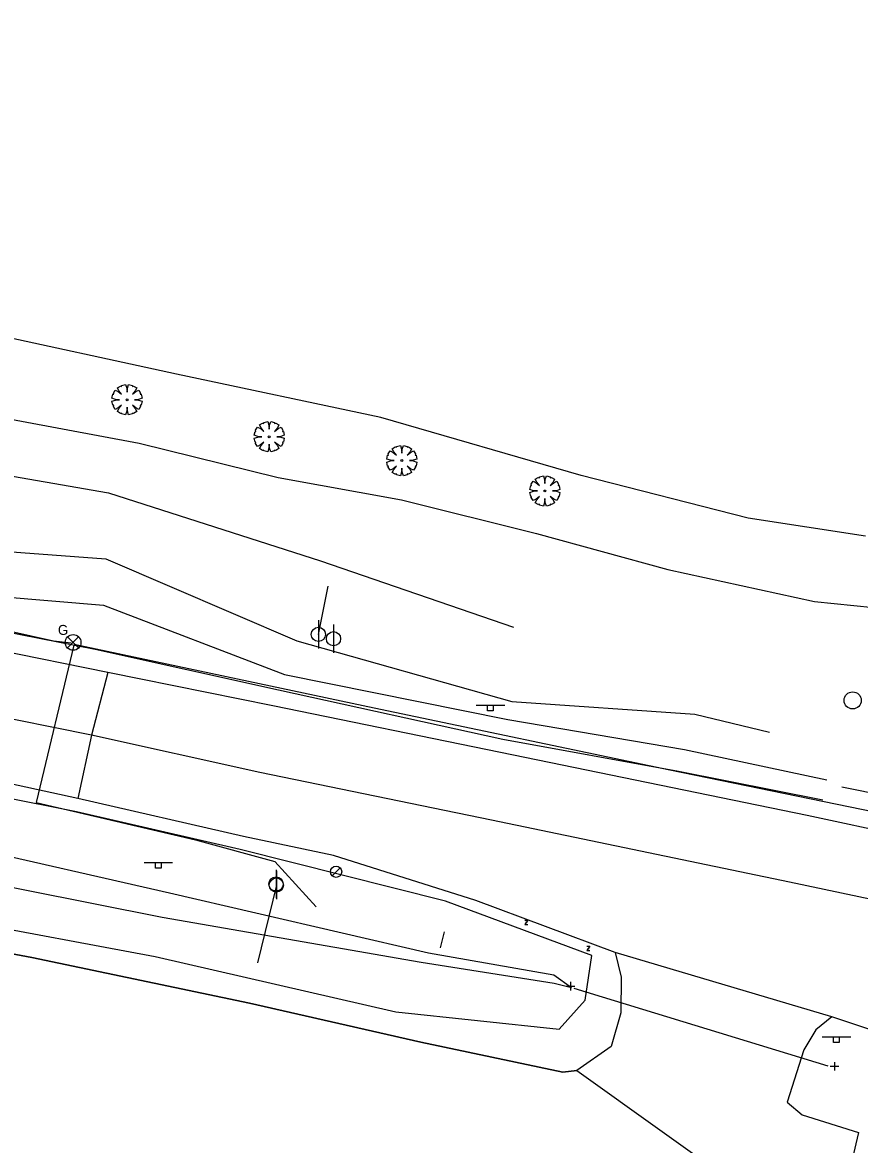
# Model space of a CAD drawing. Extents: x 1158469 to 1165378, y 609843 to 611748.
# Drawn here: x 1164983.4 to 1165130.6, y 610051.9 to 610249.2 of the extents above; entities that cross this region are included whole.
import ezdxf

# ---------------------------------------------------------------- set-up
doc = ezdxf.new("R2010")
doc.units = 0
for name, color, linetype in [('Exterior Boundary', 7, 'Continuous'), ('S_Drainage_Culvert_Top', 7, 'Continuous'), ('S_Drainage_Invert', 7, 'Continuous'), ('S_Ground_Elevation', 7, 'Continuous'), ('S_Ground_LevelString', 7, 'Continuous'), ('S_Ground_SpotElevation', 7, 'Continuous'), ('S_Property_IronPipeFound', 7, 'Continuous'), ('S_Roadway_Centerline', 7, 'Continuous'), ('S_Roadway_Drive_Paved', 7, 'Continuous'), ('S_Roadway_Edge_Pavement', 7, 'Continuous'), ('S_Traffic_Sign_DoublePost', 7, 'Continuous'), ('S_Traffic_Sign_SinglePost', 7, 'Continuous'), ('S_Trees_Decid_NonPay', 7, 'Continuous'), ('S_Utilities_Gas_Gate', 7, 'Continuous'), ('S_Utilities_GuyWire3', 7, 'Continuous'), ('S_Utilities_Pole_Power', 7, 'Continuous'), ('S_Utilities_UG_Gas_Line', 7, 'Continuous'), ('S_Utilities_UG_Water_Shutoff', 7, 'Continuous')]:
    doc.layers.add(name, color=color, linetype=linetype)

msp = doc.modelspace()

# ---------------------------------------------------------------- linework, layer by layer
at = {"layer": 'Exterior Boundary'}
for points in [[(1165131.67, 610158.89), (1165111.05, 610162.04), (1165081.66, 610169.51), (1165046.46, 610179.72), (1165010.53, 610187.31), (1164975.93, 610194.85), (1164954.17, 610199.11), (1164924.19, 610204.21), (1164911.82, 610196.02), (1164907.99, 610190.98), (1164903.83, 610193.7), (1164863.2, 610204)], [(1164887.39, 610105.37), (1164928.57, 610096.9), (1164949.13, 610091.57), (1164985.09, 610084.83), (1165023.36, 610076.76), (1165053.51, 610069.94), (1165078.44, 610064.65), (1165080.91, 610064.92), (1165125.5, 610033.08), (1165315.71, 609929.68)]]:
    msp.add_lwpolyline(points, dxfattribs=at)
at = {"layer": 'S_Drainage_Culvert_Top'}
msp.add_lwpolyline([(1165125.09, 610065.68), (1165080.42, 610079.35)], dxfattribs=at)
at = {"layer": 'S_Drainage_Invert'}
for p, q in [((1165079.82, 610080.51), (1165079.82, 610079.01)), ((1165079.07, 610079.76), (1165080.57, 610079.76)), ((1165126.2, 610066.43), (1165126.2, 610064.93)), ((1165125.45, 610065.68), (1165126.95, 610065.68))]:
    msp.add_line(p, q, dxfattribs=at)
at = {"layer": 'S_Ground_Elevation'}
for points in [[(1165131.67, 610158.89), (1165111.05, 610162.04), (1165081.66, 610169.51), (1165046.46, 610179.72), (1165010.53, 610187.31), (1164975.93, 610194.85), (1164954.17, 610199.11), (1164924.19, 610204.21), (1164911.82, 610196.02), (1164928.99, 610192.61), (1164954.02, 610185.41), (1164976.94, 610180.26), (1165003.93, 610175.22), (1165028.37, 610169.19), (1165050.08, 610165.24), (1165073.84, 610159.31), (1165096.89, 610152.98), (1165122.71, 610147.36), (1165133.09, 610146.34)], [(1164949.24, 610096.19), (1164972.18, 610091.41), (1165006.8, 610084.96), (1165049.11, 610075.28), (1165077.78, 610072.21), (1165082.39, 610077.32), (1165083.55, 610085.15), (1165057.81, 610094.68), (1165021.71, 610103.76), (1164992.93, 610110.39), (1164953.46, 610118.26), (1164916.46, 610126.06), (1164891.26, 610129.22), (1164870.42, 610136.28), (1164819.53, 610147.22), (1164777.52, 610154.18), (1164692.53, 610173.85), (1164663.65, 610179.23), (1164613.39, 610190.6), (1164600.18, 610192.25)], [(1164966.43, 610172.04), (1164998.59, 610166.47), (1165035.82, 610154.51), (1165069.8, 610142.86)], [(1164962.64, 610157.49), (1164998.12, 610154.87), (1165031.67, 610140.45), (1165069.48, 610129.78), (1165101.64, 610127.55), (1165114.79, 610124.42)], [(1165341.63, 610152.38), (1165338.28, 610137.27), (1165328.96, 610121.76), (1165325.7, 610114.21), (1165322.7, 610114.67), (1165317.16, 610108.11), (1165300.9, 610100.28), (1165278.07, 610094.59), (1165255.25, 610093.27), (1165234.36, 610095.8), (1165209.94, 610099.32), (1165192.02, 610102.23), (1165159.8, 610108.25), (1165127.49, 610114.72)], [(1164961.29, 610149.76), (1164997.7, 610146.75), (1165029.5, 610134.54), (1165068.79, 610126.62), (1165099.84, 610121.37), (1165124.88, 610116.02)], [(1164959.76, 610146.17), (1164996.21, 610138.99), (1165028.47, 610131.87), (1165067.91, 610123.16), (1165098.77, 610117.56), (1165124.14, 610112.54)], [(1164952.23, 610109.23), (1164972.73, 610104.47), (1165009.28, 610096.16), (1165054.81, 610085.61), (1165076.88, 610081.78), (1165079.99, 610079.53)], [(1164950.89, 610103.75), (1164971.74, 610099.12), (1165008, 610091.89), (1165053.56, 610083.98), (1165076.9, 610080.31), (1165079.99, 610079.53)]]:
    msp.add_lwpolyline(points, dxfattribs=at)
at = {"layer": 'S_Ground_LevelString'}
msp.add_lwpolyline([(1164998.45, 610134.89), (1164995.59, 610123.89), (1164993.19, 610112.73)], dxfattribs=at)
at = {"layer": 'S_Ground_SpotElevation'}
for p, q in [((1165071.75, 610091.39), (1165072.28, 610091.39)), ((1165072.28, 610091.39), (1165071.75, 610090.61)), ((1165071.75, 610090.61), (1165072.27, 610090.61)), ((1165071.86, 610091), (1165072.17, 610091)), ((1165082.68, 610086.8), (1165083.21, 610086.8)), ((1165083.21, 610086.8), (1165082.68, 610086.02)), ((1165082.68, 610086.02), (1165083.21, 610086.02)), ((1165082.79, 610086.41), (1165083.1, 610086.41))]:
    msp.add_line(p, q, dxfattribs=at)
at = {"layer": 'S_Property_IronPipeFound'}
msp.add_circle((1165129.41, 610130), 1.5, dxfattribs=at)
at = {"layer": 'S_Roadway_Centerline'}
msp.add_lwpolyline([(1165322.92, 610055.12), (1165282.59, 610063.58), (1165267.59, 610066.74), (1165234.97, 610073.48), (1165207.29, 610078.95), (1165170.95, 610086.9), (1165118.3, 610098.03), (1165065.91, 610108.93), (1165025.19, 610117.35), (1164995.59, 610123.89), (1164956.04, 610131.83), (1164919.32, 610140.12), (1164874.11, 610149.34), (1164822.77, 610160.96), (1164779.77, 610169.22), (1164696.7, 610187.78), (1164657.25, 610196.14), (1164616.44, 610205.3), (1164588.01, 610211.13), (1164540.84, 610220.89), (1164515.97, 610226.08), (1164470.96, 610235.38), (1164428.02, 610243.9), (1164400.81, 610249.16)], dxfattribs=at)
at = {"layer": 'S_Roadway_Drive_Paved'}
for points in [[(1165087.67, 610085.66), (1165088.73, 610081.37), (1165088.66, 610075.08), (1165086.95, 610069.17), (1165080.91, 610064.92), (1165078.44, 610064.65), (1165053.51, 610069.94), (1165023.36, 610076.76), (1164985.09, 610084.83), (1164949.13, 610091.57), (1164928.57, 610096.9), (1164887.39, 610105.37), (1164871.7, 610110.37), (1164815.65, 610122.37), (1164772.52, 610131.34), (1164687.39, 610149.15), (1164656.83, 610155.47), (1164607.36, 610165.71), (1164581.72, 610171.1)], [(1165125.74, 610074.35), (1165122.94, 610072.11), (1165120.84, 610068.57), (1165117.88, 610059.35), (1165120.55, 610057.16), (1165130.42, 610054.05), (1165125.5, 610033.08)]]:
    msp.add_lwpolyline(points, dxfattribs=at)
at = {"layer": 'S_Roadway_Edge_Pavement'}
for points in [[(1165172.21, 610098.85), (1165121.41, 610109.77), (1165067.49, 610120.81), (1165027.46, 610129.03), (1164998.45, 610134.89), (1164959.14, 610142.85), (1164919.8, 610151.45), (1164879.24, 610159.72)], [(1165176.01, 610057.63), (1165125.74, 610074.35), (1165087.67, 610085.66), (1165063.14, 610094.84), (1165038.13, 610102.71), (1165022.28, 610106.09), (1164993.19, 610112.73), (1164953.01, 610121.48), (1164917.37, 610129.44), (1164871.2, 610138.85)]]:
    msp.add_lwpolyline(points, dxfattribs=at)
at = {"layer": 'S_Traffic_Sign_DoublePost'}
msp.add_lwpolyline([(1165056.93, 610086.51), (1165057.67, 610089.29)], dxfattribs=at)
at = {"layer": 'S_Traffic_Sign_SinglePost'}
for p, q in [((1165063.23, 610129.14), (1165068.23, 610129.14)), ((1165004.83, 610101.49), (1165009.83, 610101.49)), ((1165124.06, 610070.86), (1165129.06, 610070.86))]:
    msp.add_line(p, q, dxfattribs=at)
for points in [[(1165065.23, 610129.14), (1165066.23, 610129.14), (1165066.23, 610128.14), (1165065.23, 610128.14)], [(1165006.83, 610101.49), (1165007.83, 610101.49), (1165007.83, 610100.49), (1165006.83, 610100.49)], [(1165126.06, 610070.86), (1165127.06, 610070.86), (1165127.06, 610069.86), (1165126.06, 610069.86)]]:
    msp.add_lwpolyline(points, close=True, dxfattribs=at)
at = {"layer": 'S_Trees_Decid_NonPay'}
for points in [[(1165000.5, 610182.84), (1164999.8, 610182.9), (1164999.17, 610183.11), (1164999.33, 610183.8), (1164999.49, 610183.8), (1164999.43, 610184.01), (1164999.75, 610184.54), (1165000.28, 610184.28), (1165000.87, 610183.8), (1165000.39, 610184.38), (1165000.12, 610184.92), (1165000.66, 610185.23), (1165000.87, 610185.18), (1165000.87, 610185.34), (1165001.56, 610185.5), (1165001.77, 610184.86), (1165001.82, 610184.17), (1165001.88, 610184.86), (1165002.09, 610185.5), (1165002.78, 610185.34), (1165002.78, 610185.18), (1165002.99, 610185.23), (1165003.53, 610184.92), (1165003.26, 610184.38), (1165002.78, 610183.8), (1165003.37, 610184.28), (1165003.9, 610184.54), (1165004.22, 610184.01), (1165004.16, 610183.8), (1165004.32, 610183.8), (1165004.48, 610183.11), (1165003.84, 610182.9), (1165003.15, 610182.84), (1165003.84, 610182.79), (1165004.48, 610182.58), (1165004.32, 610181.89), (1165004.16, 610181.89), (1165004.22, 610181.67), (1165003.9, 610181.14), (1165003.37, 610181.41), (1165002.78, 610181.89), (1165003.26, 610181.3), (1165003.53, 610180.77), (1165002.99, 610180.45), (1165002.78, 610180.5), (1165002.78, 610180.34), (1165002.09, 610180.18), (1165001.88, 610180.82), (1165001.82, 610181.51), (1165001.77, 610180.82), (1165001.56, 610180.18), (1165000.87, 610180.34), (1165000.87, 610180.5), (1165000.66, 610180.45), (1165000.12, 610180.77), (1165000.39, 610181.3), (1165000.87, 610181.89), (1165000.28, 610181.41), (1164999.75, 610181.14), (1164999.43, 610181.67), (1164999.49, 610181.89), (1164999.33, 610181.89), (1164999.17, 610182.58), (1164999.8, 610182.79), (1165000.5, 610182.84)], [(1165025.5, 610176.34), (1165024.81, 610176.39), (1165024.17, 610176.6), (1165024.33, 610177.29), (1165024.49, 610177.29), (1165024.43, 610177.5), (1165024.75, 610178.04), (1165025.28, 610177.77), (1165025.87, 610177.29), (1165025.39, 610177.88), (1165025.12, 610178.41), (1165025.66, 610178.73), (1165025.87, 610178.67), (1165025.87, 610178.83), (1165026.56, 610178.99), (1165026.77, 610178.36), (1165026.83, 610177.66), (1165026.88, 610178.36), (1165027.09, 610178.99), (1165027.78, 610178.83), (1165027.78, 610178.67), (1165027.99, 610178.73), (1165028.53, 610178.41), (1165028.26, 610177.88), (1165027.78, 610177.29), (1165028.37, 610177.77), (1165028.9, 610178.04), (1165029.22, 610177.5), (1165029.16, 610177.29), (1165029.32, 610177.29), (1165029.48, 610176.6), (1165028.84, 610176.39), (1165028.15, 610176.34), (1165028.84, 610176.28), (1165029.48, 610176.07), (1165029.32, 610175.38), (1165029.16, 610175.38), (1165029.22, 610175.17), (1165028.9, 610174.63), (1165028.37, 610174.9), (1165027.78, 610175.38), (1165028.26, 610174.79), (1165028.53, 610174.26), (1165027.99, 610173.94), (1165027.78, 610174), (1165027.78, 610173.84), (1165027.09, 610173.68), (1165026.88, 610174.32), (1165026.83, 610175.01), (1165026.77, 610174.32), (1165026.56, 610173.68), (1165025.87, 610173.84), (1165025.87, 610174), (1165025.66, 610173.94), (1165025.12, 610174.26), (1165025.39, 610174.79), (1165025.87, 610175.38), (1165025.28, 610174.9), (1165024.75, 610174.63), (1165024.43, 610175.17), (1165024.49, 610175.38), (1165024.33, 610175.38), (1165024.17, 610176.07), (1165024.81, 610176.28), (1165025.5, 610176.34)], [(1165048.81, 610172.15), (1165048.12, 610172.2), (1165047.49, 610172.41), (1165047.65, 610173.1), (1165047.81, 610173.1), (1165047.75, 610173.32), (1165048.07, 610173.85), (1165048.6, 610173.58), (1165049.19, 610173.1), (1165048.71, 610173.69), (1165048.44, 610174.22), (1165048.97, 610174.54), (1165049.19, 610174.48), (1165049.19, 610174.64), (1165049.88, 610174.8), (1165050.09, 610174.17), (1165050.14, 610173.47), (1165050.2, 610174.17), (1165050.41, 610174.8), (1165051.1, 610174.64), (1165051.1, 610174.48), (1165051.31, 610174.54), (1165051.85, 610174.22), (1165051.58, 610173.69), (1165051.1, 610173.1), (1165051.68, 610173.58), (1165052.22, 610173.85), (1165052.54, 610173.32), (1165052.48, 610173.1), (1165052.64, 610173.1), (1165052.8, 610172.41), (1165052.16, 610172.2), (1165051.47, 610172.15), (1165052.16, 610172.09), (1165052.8, 610171.88), (1165052.64, 610171.19), (1165052.48, 610171.19), (1165052.54, 610170.98), (1165052.22, 610170.44), (1165051.68, 610170.71), (1165051.1, 610171.19), (1165051.58, 610170.6), (1165051.85, 610170.07), (1165051.31, 610169.75), (1165051.1, 610169.81), (1165051.1, 610169.65), (1165050.41, 610169.49), (1165050.2, 610170.13), (1165050.14, 610170.82), (1165050.09, 610170.13), (1165049.88, 610169.49), (1165049.19, 610169.65), (1165049.19, 610169.81), (1165048.97, 610169.75), (1165048.44, 610170.07), (1165048.71, 610170.6), (1165049.19, 610171.19), (1165048.6, 610170.71), (1165048.07, 610170.44), (1165047.75, 610170.98), (1165047.81, 610171.19), (1165047.65, 610171.19), (1165047.49, 610171.88), (1165048.12, 610172.09), (1165048.81, 610172.15)], [(1165073.97, 610166.81), (1165073.27, 610166.86), (1165072.64, 610167.07), (1165072.8, 610167.76), (1165072.96, 610167.76), (1165072.9, 610167.98), (1165073.22, 610168.51), (1165073.75, 610168.24), (1165074.34, 610167.76), (1165073.86, 610168.35), (1165073.59, 610168.88), (1165074.13, 610169.2), (1165074.34, 610169.14), (1165074.34, 610169.3), (1165075.03, 610169.46), (1165075.24, 610168.83), (1165075.29, 610168.13), (1165075.35, 610168.83), (1165075.56, 610169.46), (1165076.25, 610169.3), (1165076.25, 610169.14), (1165076.46, 610169.2), (1165077, 610168.88), (1165076.73, 610168.35), (1165076.25, 610167.76), (1165076.84, 610168.24), (1165077.37, 610168.51), (1165077.69, 610167.98), (1165077.63, 610167.76), (1165077.79, 610167.76), (1165077.95, 610167.07), (1165077.31, 610166.86), (1165076.62, 610166.81), (1165077.31, 610166.75), (1165077.95, 610166.54), (1165077.79, 610165.85), (1165077.63, 610165.85), (1165077.69, 610165.64), (1165077.37, 610165.11), (1165076.84, 610165.37), (1165076.25, 610165.85), (1165076.73, 610165.26), (1165077, 610164.73), (1165076.46, 610164.41), (1165076.25, 610164.47), (1165076.25, 610164.31), (1165075.56, 610164.15), (1165075.35, 610164.79), (1165075.29, 610165.48), (1165075.24, 610164.79), (1165075.03, 610164.15), (1165074.34, 610164.31), (1165074.34, 610164.47), (1165074.13, 610164.41), (1165073.59, 610164.73), (1165073.86, 610165.26), (1165074.34, 610165.85), (1165073.75, 610165.37), (1165073.22, 610165.11), (1165072.9, 610165.64), (1165072.96, 610165.85), (1165072.8, 610165.85), (1165072.64, 610166.54), (1165073.27, 610166.75), (1165073.97, 610166.81)]]:
    msp.add_lwpolyline(points, dxfattribs=at)
for centre in [(1165001.82, 610182.84), (1165026.82, 610176.34), (1165050.14, 610172.15), (1165075.29, 610166.81)]:
    msp.add_circle(centre, 0.167, dxfattribs=at)
at = {"layer": 'S_Utilities_Gas_Gate'}
for p, q in [((1164991.37, 610141.15), (1164993.32, 610139.21)), ((1164991.37, 610139.21), (1164993.32, 610141.15))]:
    msp.add_line(p, q, dxfattribs=at)
msp.add_circle((1164992.35, 610140.18), 1.38, dxfattribs=at)
at = {"layer": 'S_Utilities_GuyWire3'}
for points in [[(1165035.47, 610141.6), (1165037.17, 610150.09)], [(1165028.09, 610097.53), (1165028.07, 610097.6)], [(1165028.09, 610097.53), (1165024.74, 610083.85)]]:
    msp.add_lwpolyline(points, dxfattribs=at)
at = {"layer": 'S_Utilities_Pole_Power'}
for p, q in [((1165035.47, 610144.1), (1165035.47, 610139.1)), ((1165038.12, 610143.34), (1165038.12, 610138.34)), ((1165028.02, 610100.22), (1165028.02, 610095.22)), ((1165028.09, 610100.03), (1165028.09, 610095.03))]:
    msp.add_line(p, q, dxfattribs=at)
for centre in [(1165035.47, 610141.6), (1165038.12, 610140.84), (1165028.02, 610097.72), (1165028.09, 610097.53)]:
    msp.add_circle(centre, 1.25, dxfattribs=at)
at = {"layer": 'S_Utilities_UG_Gas_Line'}
for points in [[(1164523.25, 610240.99), (1164578.61, 610230.52), (1164633.3, 610218.87), (1164687.87, 610206.09), (1164725.23, 610197.92), (1164780.39, 610186.82), (1164833.41, 610174.66), (1164886.88, 610163.44), (1164937.79, 610151.89), (1164988.92, 610140.46), (1164992, 610140.14)], [(1164992.49, 610139.72), (1164985.83, 610112.04), (1165013.84, 610105.48), (1165027.8, 610101.7), (1165035.06, 610093.72)], [(1164992.54, 610139.89), (1165045.26, 610128.69), (1165097.28, 610117.79), (1165146.7, 610107.65), (1165197.61, 610096.36), (1165229.6, 610091.61), (1165255.24, 610091.77), (1165291.62, 610097.45), (1165319.94, 610112.7), (1165334.73, 610139.41)]]:
    msp.add_lwpolyline(points, dxfattribs=at)
at = {"layer": 'S_Utilities_UG_Water_Shutoff'}
msp.add_line((1165037.87, 610099.18), (1165039.28, 610100.59), dxfattribs=at)
msp.add_circle((1165038.58, 610099.88), 1, dxfattribs=at)

# ---------------------------------------------------------------- texts
at = {"layer": 'S_Utilities_Gas_Gate'}
msp.add_text('G', height=1.75, dxfattribs=at).set_placement((1164989.67, 610141.51))

doc.saveas('drawing.dxf')
